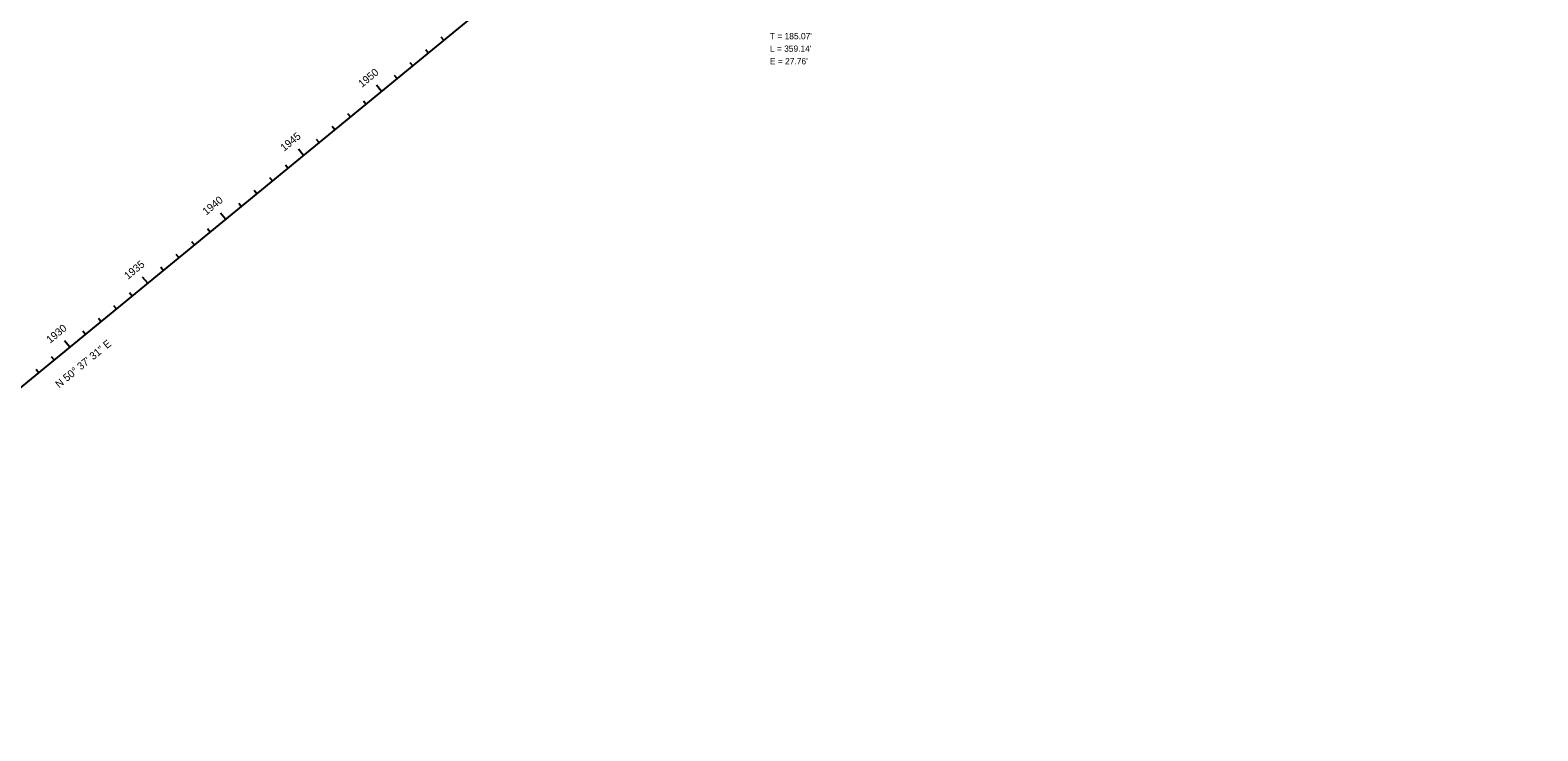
# Model space of a CAD drawing. Extents: x 1280727 to 1452510, y 526233 to 601451.
# Drawn here: x 1445022 to 1452500, y 592997 to 596472 of the extents above; entities that cross this region are included whole.
import ezdxf

# ---------------------------------------------------------------- set-up
doc = ezdxf.new("R2010")
doc.units = 0
for name, color, linetype in [('Level 63', 7, 'Continuous'), ('RW_X_CL', 7, 'Continuous'), ('RW_X_CL_500_Stations', 7, 'Continuous'), ('SH_Text', 7, 'Continuous')]:
    doc.layers.add(name, color=color, linetype=linetype)

msp = doc.modelspace()

# ---------------------------------------------------------------- linework, layer by layer
at = {"layer": 'RW_X_CL'}
msp.add_line((1442900, 592996.6), (1452499.9, 600875), dxfattribs=at)
at = {"layer": 'RW_X_CL_500_Stations'}
for p, q in [((1447074.2, 596422.3), (1447061.6, 596437.8)), ((1446996.9, 596358.9), (1446984.3, 596374.3)), ((1446919.6, 596295.4), (1446907, 596310.9)), ((1446765, 596168.6), (1446739.7, 596199.5)), ((1446842.3, 596232), (1446829.6, 596247.5)), ((1446687.7, 596105.1), (1446675, 596120.6)), ((1446610.4, 596041.7), (1446597.7, 596057.1)), ((1446533.1, 595978.2), (1446520.4, 595993.7)), ((1446378.5, 595851.4), (1446353.2, 595882.3)), ((1446455.8, 595914.8), (1446443.1, 595930.3)), ((1446223.9, 595724.5), (1446211.2, 595739.9)), ((1446301.2, 595787.9), (1446288.5, 595803.4)), ((1446146.6, 595661), (1446133.9, 595676.5)), ((1446069.3, 595597.6), (1446056.6, 595613.1)), ((1445992, 595534.2), (1445966.6, 595565.1)), ((1445914.7, 595470.7), (1445902, 595486.2)), ((1445760.1, 595343.9), (1445747.4, 595359.3)), ((1445837.4, 595407.3), (1445824.7, 595422.8)), ((1445682.8, 595280.4), (1445670.1, 595295.9)), ((1445605.5, 595217), (1445580.1, 595247.9)), ((1445528.2, 595153.5), (1445515.5, 595169)), ((1445450.9, 595090.1), (1445438.2, 595105.6)), ((1445373.6, 595026.7), (1445360.9, 595042.1)), ((1445219, 594899.8), (1445193.6, 594930.7)), ((1445296.3, 594963.2), (1445283.6, 594978.7)), ((1445141.7, 594836.3), (1445129, 594851.8)), ((1445064.4, 594772.9), (1445051.7, 594788.4))]:
    msp.add_line(p, q, dxfattribs=at)

# ---------------------------------------------------------------- texts
at = {"layer": 'Level 63'}
for s, p in [("T = 185.07'", (1448691.1, 596427.4)), ("L = 359.14'", (1448691.1, 596365)), ("E = 27.76'", (1448691.1, 596302.6))]:
    msp.add_text(s, height=31.2, dxfattribs=at).set_placement(p)
at = {"layer": 'RW_X_CL_500_Stations'}
for s, p in [('1950', (1446668.4, 596186.3)), ('1945', (1446282.3, 595869.4)), ('1940', (1445896.2, 595552.5)), ('1935', (1445507.8, 595233.8)), ('1930', (1445121.7, 594916.9))]:
    msp.add_text(s, height=37.5, rotation=39.37484, dxfattribs=at).set_placement(p)
at = {"layer": 'SH_Text'}
msp.add_text('N 50° 37\' 31" E', height=37.5, rotation=39.37484, dxfattribs=at).set_placement((1445166, 594695.2))

doc.saveas('drawing.dxf')
